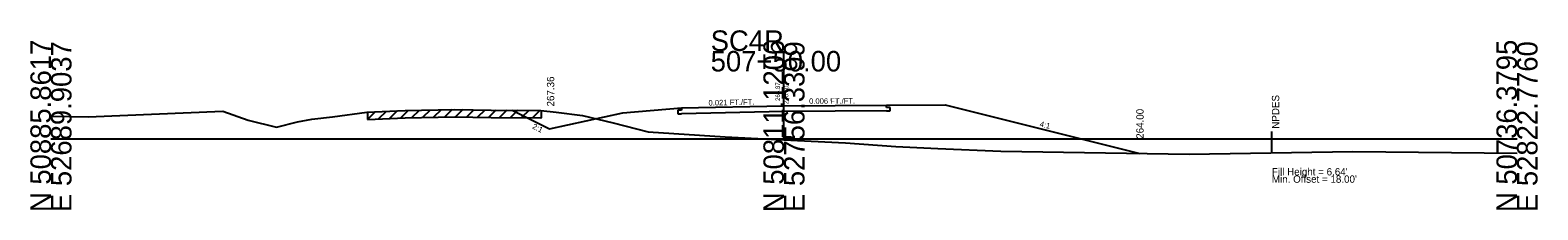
# Model space of a CAD drawing. Extents: x 7498 to 13027, y 90095 to 109625.
# Drawn here: x 8521.2 to 8726.8, y 97595.5 to 97620 of the extents above; entities that cross this region are included whole.
import ezdxf

# ---------------------------------------------------------------- set-up
doc = ezdxf.new("R2010")
doc.units = 0
for name, color, linetype in [('Level 10', 7, 'Continuous'), ('Level 11', 7, 'Continuous'), ('Level 12', 7, 'Continuous'), ('Level 32', 7, 'Continuous'), ('Level 33', 7, 'Continuous'), ('Level 50', 7, 'Continuous'), ('Level 55', 7, 'Continuous'), ('Level 59', 7, 'Continuous'), ('Level 6', 7, 'Continuous'), ('Level 60', 7, 'Continuous'), ('Level 61', 7, 'Continuous'), ('Level 63', 7, 'Continuous'), ('Level 7', 7, 'Continuous')]:
    doc.layers.add(name, color=color, linetype=linetype)

msp = doc.modelspace()

# ---------------------------------------------------------------- linework, layer by layer
at = {"layer": 'Level 11'}
for p, q in [((8609.99, 97609.07), (8609.49, 97609.05)), ((8609.49, 97609.05), (8609.49, 97608.57)), ((8609.49, 97608.57), (8609.99, 97608.59)), ((8609.99, 97609.37), (8609.99, 97609.07)), ((8637.99, 97609.45), (8637.99, 97609.75)), ((8638.49, 97609.45), (8637.99, 97609.45)), ((8637.99, 97608.97), (8638.49, 97608.97)), ((8638.49, 97608.97), (8638.49, 97609.45))]:
    msp.add_line(p, q, dxfattribs=at)
at = {"layer": 'Level 12'}
for p, q in [((8623.99, 97608.88), (8609.99, 97608.59)), ((8637.99, 97608.97), (8623.99, 97608.88))]:
    msp.add_line(p, q, dxfattribs=at)
at = {"layer": 'Level 55'}
msp.add_line((8690.55, 97603.16), (8690.55, 97606.16), dxfattribs=at)
at = {"layer": 'Level 59'}
for p, q in [((8609.99, 97609.37), (8623.99, 97609.66)), ((8623.99, 97609.66), (8637.99, 97609.75))]:
    msp.add_line(p, q, dxfattribs=at)
at = {"layer": 'Level 6'}
for p, q in [((8601.99, 97608.7), (8609.99, 97609.37)), ((8637.99, 97609.75), (8645.99, 97609.8))]:
    msp.add_line(p, q, dxfattribs=at)
at = {"layer": 'Level 60'}
for p, q in [((8523.99, 97608.23), (8529.08, 97608.15)), ((8529.08, 97608.15), (8547.46, 97608.93)), ((8547.46, 97608.93), (8550.88, 97607.69)), ((8562.38, 97608.18), (8567.06, 97608.81)), ((8567.06, 97608.81), (8572.29, 97609)), ((8572.29, 97609), (8579.05, 97609.15)), ((8579.05, 97609.15), (8584.06, 97609.07)), ((8584.06, 97609.07), (8590.82, 97609.03)), ((8590.82, 97609.03), (8592.92, 97608.79)), ((8592.92, 97608.79), (8596.52, 97608.34)), ((8596.52, 97608.34), (8600.69, 97607.33)), ((8550.88, 97607.69), (8554.75, 97606.76)), ((8554.75, 97606.76), (8557.61, 97607.48)), ((8557.61, 97607.48), (8559.56, 97607.84)), ((8559.56, 97607.84), (8562.38, 97608.18)), ((8600.69, 97607.33), (8605.45, 97606.11)), ((8605.45, 97606.11), (8615.98, 97605.43)), ((8615.98, 97605.43), (8623.99, 97605.03)), ((8623.99, 97605.03), (8632.39, 97604.6)), ((8632.39, 97604.6), (8639.26, 97604.12)), ((8639.26, 97604.12), (8644.96, 97603.84)), ((8644.96, 97603.84), (8653.57, 97603.45)), ((8653.57, 97603.45), (8679.27, 97603.06)), ((8679.27, 97603.06), (8701.59, 97603.44)), ((8701.59, 97603.44), (8723.99, 97603.18))]:
    msp.add_line(p, q, dxfattribs=at)
at = {"layer": 'Level 61'}
for p, q in [((8568.22, 97608.85), (8567.18, 97607.81)), ((8567.18, 97608.81), (8567.18, 97607.81)), ((8569.72, 97608.9), (8568.68, 97607.87)), ((8571.22, 97608.96), (8570.18, 97607.92)), ((8572.72, 97609.01), (8571.68, 97607.98)), ((8574.21, 97609.04), (8573.18, 97608.02)), ((8575.71, 97609.08), (8574.68, 97608.05)), ((8577.21, 97609.11), (8576.18, 97608.09)), ((8578.71, 97609.15), (8577.68, 97608.12)), ((8580.17, 97609.14), (8579.18, 97608.15)), ((8581.67, 97609.11), (8580.68, 97608.13)), ((8583.17, 97609.09), (8582.18, 97608.1)), ((8584.67, 97609.07), (8583.68, 97608.08)), ((8586.18, 97609.06), (8585.18, 97608.07)), ((8587.68, 97609.05), (8586.68, 97608.06)), ((8589.18, 97609.04), (8588.18, 97608.05)), ((8590.68, 97609.03), (8589.68, 97608.04)), ((8590.9, 97608.02), (8590.9, 97609.02)), ((8567.18, 97607.81), (8572.29, 97608)), ((8572.29, 97608), (8579.05, 97608.15)), ((8579.05, 97608.15), (8584.06, 97608.07)), ((8584.06, 97608.07), (8590.82, 97608.03)), ((8590.82, 97608.03), (8590.9, 97608.02))]:
    msp.add_line(p, q, dxfattribs=at)
at = {"layer": 'Level 63'}
for p, q in [((8623.99, 97605.16), (8623.99, 97617.15)), ((8523.99, 97605.16), (8623.99, 97605.16)), ((8623.99, 97605.16), (8723.99, 97605.16))]:
    msp.add_line(p, q, dxfattribs=at)
at = {"layer": 'Level 7'}
for p, q in [((8586.91, 97609.06), (8591.99, 97606.51)), ((8591.99, 97606.51), (8601.99, 97608.7)), ((8645.99, 97609.8), (8672.55, 97603.16))]:
    msp.add_line(p, q, dxfattribs=at)

# ---------------------------------------------------------------- texts
at = {"layer": 'Level 10'}
msp.add_text('265.87', height=0.6, rotation=90, dxfattribs=at).set_placement((8623.43, 97610.33))
at = {"layer": 'Level 32'}
for s, rotation, p in [('0.021 FT./FT.', 1.1916, (8613.7, 97609.69)), ('0.006 FT./FT.', 0.3723, (8627.42, 97609.93)), ('2:1', 333.435, (8589.58, 97606.61)), ('4:1', 345.9638, (8658.82, 97606.85))]:
    msp.add_text(s, height=0.75, rotation=rotation, dxfattribs=at).set_placement(p)
at = {"layer": 'Level 33'}
for s, p in [('267.36', (8592.65, 97609.57)), ('264.00', (8673.05, 97605.16))]:
    msp.add_text(s, height=1, rotation=90, dxfattribs=at).set_placement(p)
at = {"layer": 'Level 50'}
msp.add_text(' NPDES', height=1, rotation=90, dxfattribs=at).set_placement((8691.55, 97606.16))
for s, p in [("Fill Height = 6.64' ", (8690.55, 97600.16)), ("Min. Offset = 18.00' ", (8690.55, 97599.16))]:
    msp.add_text(s, height=1, dxfattribs=at).set_placement(p)
at = {"layer": 'Level 59'}
msp.add_text(' 270.50', height=0.6, rotation=90, dxfattribs=at).set_placement((8624.59, 97609.66))
at = {"layer": 'Level 63'}
for s, p in [('N 50885.8617', (8523.99, 97595.16)), ('N 50811.1206', (8623.99, 97595.15)), ('N 50736.3795', (8723.99, 97595.16)), ('E 52689.9037', (8526.79, 97595.16)), ('E 52756.3399', (8626.79, 97595.16)), ('E 52822.7760', (8726.79, 97595.16))]:
    msp.add_text(s, height=2.8, rotation=90, dxfattribs=at).set_placement(p)
for s, p in [('SC4R', (8613.99, 97617.15)), ('507+50.00', (8613.99, 97614.35))]:
    msp.add_text(s, height=2.8, dxfattribs=at).set_placement(p)

doc.saveas('drawing.dxf')
